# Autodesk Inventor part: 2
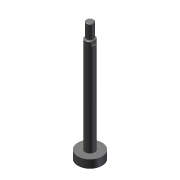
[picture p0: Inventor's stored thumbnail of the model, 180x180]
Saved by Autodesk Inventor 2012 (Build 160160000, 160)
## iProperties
Company: CAD-Verlag
Created: 2004-09
Part Number: 2
Document SubType Name: Modeling
Designer: Greiling
Manufacturer: Standard
Standards Organization: Custom
Density: 1 g/cm^3
Checked By: Jürgen Kronas
Stock Number: 10-10011
Material: Standard
Übersetzungsnorm: STEP AP203
Dateiname: s:/PartAssembly/iodir/wkb1973826_no0//0//532740_DNCB_40_80_PPV_A.stp
Postprozessor: Build: 096e, Release: 9 RTM - Date: Thu 06/17/2004
Gesendete Einheiten: CENTIMETERS
Unbestimmtheit: 0.0
Author: Juergen Kronas
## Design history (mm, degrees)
feature "Basis1"
node "Volumenkörper1"
node "Volumenkörpern"
node "Oberflächenkörpern"
